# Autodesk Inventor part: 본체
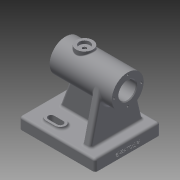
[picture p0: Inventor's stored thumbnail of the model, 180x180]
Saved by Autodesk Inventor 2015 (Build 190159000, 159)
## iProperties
Created: 2022-06
Part Number: 본체
Material: 일반
Document SubType Name: Modeling
Designer: 104-111
Density: 1 g/cm^3
Appearance: 기본값
Author: 104-111
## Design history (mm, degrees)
sketch "스케치1"
  geometry: L1 (0, 0)-(-100, 0); L2 (-100, 0)-(-100, 86); L3 (-100, 86)-(0, 86); L4 (0, 86)-(0, 0)
  constraints: 8 end point, 2 parallel, 1 horizontal, 1 perpendicular
  dimensions: "d0" = 100 distance of L1.start L1.end; "d1" = 86 distance of L3.end L1.start
extrude "돌출1" new body sketch "스케치1" distance "d2" = 15; taper "d3" = 0 deg
sketch "스케치2"
  geometry: L1 (0, 0)-(0, 86) reference; L2 (0, 86)-(-100, 86) reference; L3 (-100, 86)-(-100, 0) reference; L4 (-74, 70)-(-62, 70); L5 (-74, 63)-(-62, 63); L6 (-62, 77)-(-74, 77); L7 (-74, 16)-(-62, 16); L8 (-74, 9)-(-62, 9); L9 (-62, 23)-(-74, 23); L10 (-100, 43)-(0, 43); A1 r 7 centre (-74, 70) between (-74, 77) and (-74, 63); A2 r 7 centre (-62, 70) between (-62, 63) and (-62, 77); A3 r 7 centre (-74, 16) between (-74, 23) and (-74, 9); A4 r 7 centre (-62, 16) between (-62, 9) and (-62, 23); 2 further points
  constraints: 18 end point, 8 point on circle, 8 tangent, 4 centre point, 4 midpoint, 3 parallel, 1 horizontal
  dimensions: "d4" = 12 distance of L6.start L6.end; "d5" = 12 distance of L9.start L9.end; "d6" = 54 distance of point (-68, 16) point (-68, 70); "d7" = 16 distance from line of L2 point (-68, 70); "d8" = 26 distance from line of L3 L6.end; "d9" = 26 distance from line of L3 L8.start; "d10" = 14 distance between parallel lines of L6 L5; "d11" = 14 distance between parallel lines of L8 L9
extrude "돌출2" join sketch "스케치2" distance "d12" = 3; taper "d13" = 0 deg
sketch "스케치3"
  geometry: L1 (-74, 70)-(-62, 70); L2 (-74, 66)-(-62, 66); L3 (-62, 74)-(-74, 74); A1 r 7 centre (-62, 70) between (-62, 63) and (-62, 77) reference; A2 r 7 centre (-74, 70) between (-74, 77) and (-74, 63) reference; A3 r 4 centre (-74, 70) between (-74, 74) and (-74, 66); A4 r 4 centre (-62, 70) between (-62, 66) and (-62, 74); 2 further points
  constraints: 8 end point, 4 point on circle, 4 tangent, 2 centre point, 1 horizontal, 1 midpoint, 1 parallel
  dimensions: "d14" = 8 distance between parallel lines of L2 L3
extrude "돌출3" cut sketch "스케치3" stored distance "d15" = 3; taper "d16" = 0 deg
sketch "스케치4"
  geometry: L1 (-74, 16)-(-62, 16); L2 (-74, 20)-(-62, 20); L3 (-62, 12)-(-74, 12); A1 r 7 centre (-62, 16) between (-62, 9) and (-62, 23) reference; A2 r 7 centre (-74, 16) between (-74, 23) and (-74, 9) reference; A3 r 4 centre (-74, 16) between (-74, 20) and (-74, 12); A4 r 4 centre (-62, 16) between (-62, 12) and (-62, 20); 2 further points
  constraints: 8 end point, 4 point on circle, 4 tangent, 2 centre point, 1 horizontal, 1 midpoint, 1 parallel
  dimensions: "d17" = 8 distance between parallel lines of L2 L3
extrude "돌출4" cut sketch "스케치4" stored distance "d18" = 3; taper "d19" = 0 deg
sketch "스케치5"
  geometry: L1 (0, 0)-(0, 86) reference; L2 (-100, 86)-(-100, 0) reference; L3 (-85, 48)-(-15, 48); L4 (-15, 48)-(-15, 38); L5 (-15, 38)-(-85, 38); L6 (-85, 38)-(-85, 48); L7 (-100, 43)-(0, 43)
  constraints: 10 end point, 2 midpoint, 2 parallel, 1 horizontal, 1 perpendicular
  dimensions: "d20" = 10 distance between parallel lines of L5 L3; "d21" = 5 distance between parallel lines of L7 L3; "d22" = 15 distance between parallel lines of L2 L6; "d23" = 70 distance of L3.start L3.end
extrude "돌출5" join sketch "스케치5" distance "d24" = 57; taper "d25" = 0 deg
sketch "스케치6"
  geometry: L1 (-57, 0)-(-57, 10) reference; L2 (0, 0)-(-57, 0) reference; L3 (0, 48)-(0, -38) reference; L4 (15, -38)-(0, -38) reference; L5 (0, -38)-(0, 48) reference; L6 (-57, 5)-(21.35, 5); L7 (0, -30)-(-61.814, -15.441); L8 (0, 40)-(-61.814, 25.441); L9 (15, 48)-(0, 48) reference; L10 (-36, 0)-(0, 0); A1 r 21 centre (-57, 5) between (-61.814, -15.441) and (-61.814, 25.441); 1 further point
  constraints: 8 end point, 3 point on line, 2 horizontal, 2 point on circle, 2 tangent, 1 centre point, 1 midpoint
  dimensions: "d26" = 42 diameter of A1; "d28" = 8 distance from line of L9 L8.start; "d29" = 8 distance from line of L7.start L4
extrude "돌출6" join sketch "스케치6" distance "d30" = 10; taper "d31" = 0 deg
sketch "스케치7"
  geometry: C1 r 21 at (0, 5); A1 r 21 centre (0, 5) between (20.396, 10) and (-4.814, 25.441) reference; 1 further point
  constraints: 1 centre point, 1 coincident
  dimensions: "d32" = 42 diameter of C1
extrude "돌출7" join sketch "스케치7" distance "d33" = 15; taper "d35" = 0 deg; dims "d34" = 67, "d36" = 0
feature "면 기울기1" dims angle "d37" = 20 deg
sketch "스케치8"
  geometry: C1 r 21 at (0, 0) reference; C2 r 11.5 at (0, 0); 1 further point
  constraints: 1 centre point, 1 coincident
  dimensions: "d38" = 23 diameter of C2
extrude "돌출8" cut sketch "스케치8" distance "d39" = 20; taper "d40" = 0 deg
sketch "스케치9"
  geometry: C1 r 11.5 at (0, 0) reference; C2 r 14.5 at (0, 0); 1 further point
  constraints: 1 centre point, 1 coincident
  dimensions: "d41" = 29 diameter of C2
extrude "돌출9" cut sketch "스케치9" distance "d42" = 62; taper "d43" = 0 deg
sketch "스케치10"
  geometry: C1 r 11.5 at (0, 0) reference; 2 further points
  constraints: 1 horizontal alignment
  dimensions: "d44" = 18 distance of point (-18, 0) C1.centre
hole "구멍1" sketch "스케치10" at (-18, 0) diameter "d45" = 2.459; stored, may be unused: countersink angle "d49" = 90 deg, drill point angle "d51" = 118 deg; dims "d46" = 8, "d47" = 4, "d48" = 2, "d50" = 10.8
node "작업 평면1"
node "작업 평면2"
sketch "스케치12"
  geometry: L1 (82, 22)-(82, 64) reference; L2 (25, 38)-(71.677, 38) reference; L3 (25, 22.559)-(25, 38) reference; L4 (15, 22.559)-(25, 22.559) reference; L5 (15, 63.441)-(15, 22.559) reference; L6 (15, 63.441)-(25, 63.441) reference; L7 (25, 48)-(25, 63.441) reference; L8 (71.677, 48)-(25, 48) reference; L9 (0, 64)-(0, 22) reference; L10 (82, 64)-(0, 64) reference; L11 (82, 22)-(0, 22) reference; C1 r 11 at (57, 43); 2 further points; 1 other entity
  constraints: 1 centre point, 1 other
  dimensions: "d56" = 22 diameter of C1; "d57" = 25 distance from line of L1 C1.centre; "d58" = 21 distance from line of L11 C1.centre
extrude "돌출10" join sketch "스케치12" stored distance "d59" = 62; taper "d60" = 0 deg
sketch "스케치13"
  geometry: C1 r 11 at (0, 0) reference; 1 further point
hole "구멍2" sketch "스케치13" at (0, 0) diameter "d61" = 4.917; stored, may be unused: countersink angle "d65" = 90 deg, drill point angle "d67" = 118 deg; dims "d62" = 30, "d63" = 14, "d64" = 4, "d66" = 30
fillet "모깎기1" dims "d68" = 1
fillet "모깎기2" dims "d69" = 3
fillet "모깎기3" dims "d70" = 3
fillet "모깎기4" dims "d71" = 3
fillet "모깎기5" dims "d72" = 3
fillet "모깎기6" dims "d73" = 3
fillet "모깎기7" dims "d74" = 3
chamfer "모따기1" distance "d75" = 1; stored, may be unused: second distance "d76" = 2, angle "d77" = 45 deg
sketch "스케치14"
  geometry: L1 (0, 80)-(0, 0) reference; C1 r 1.23 at (-54, 40) reference; 2 further points
  constraints: 1 horizontal alignment, 1 other
  dimensions: "d80" = 6 distance from line of point (-6, 40) L1
feature "엠보싱1" sketch "스케치14" dims "d0" = 100, "d1" = 86, "d4" = 12, "d5" = 12, "d6" = 54, "d7" = 16, "d8" = 26, "d9" = 26, "d10" = 14, "d11" = 14, "d81" = 0.5, "d82" = 0
node "솔리드1"
pattern_circular "원형 패턴1" dims angle "d53" = 360 deg
mirror "대칭1"
node "투영된 루프1"
other parameters: "d55" = -96
